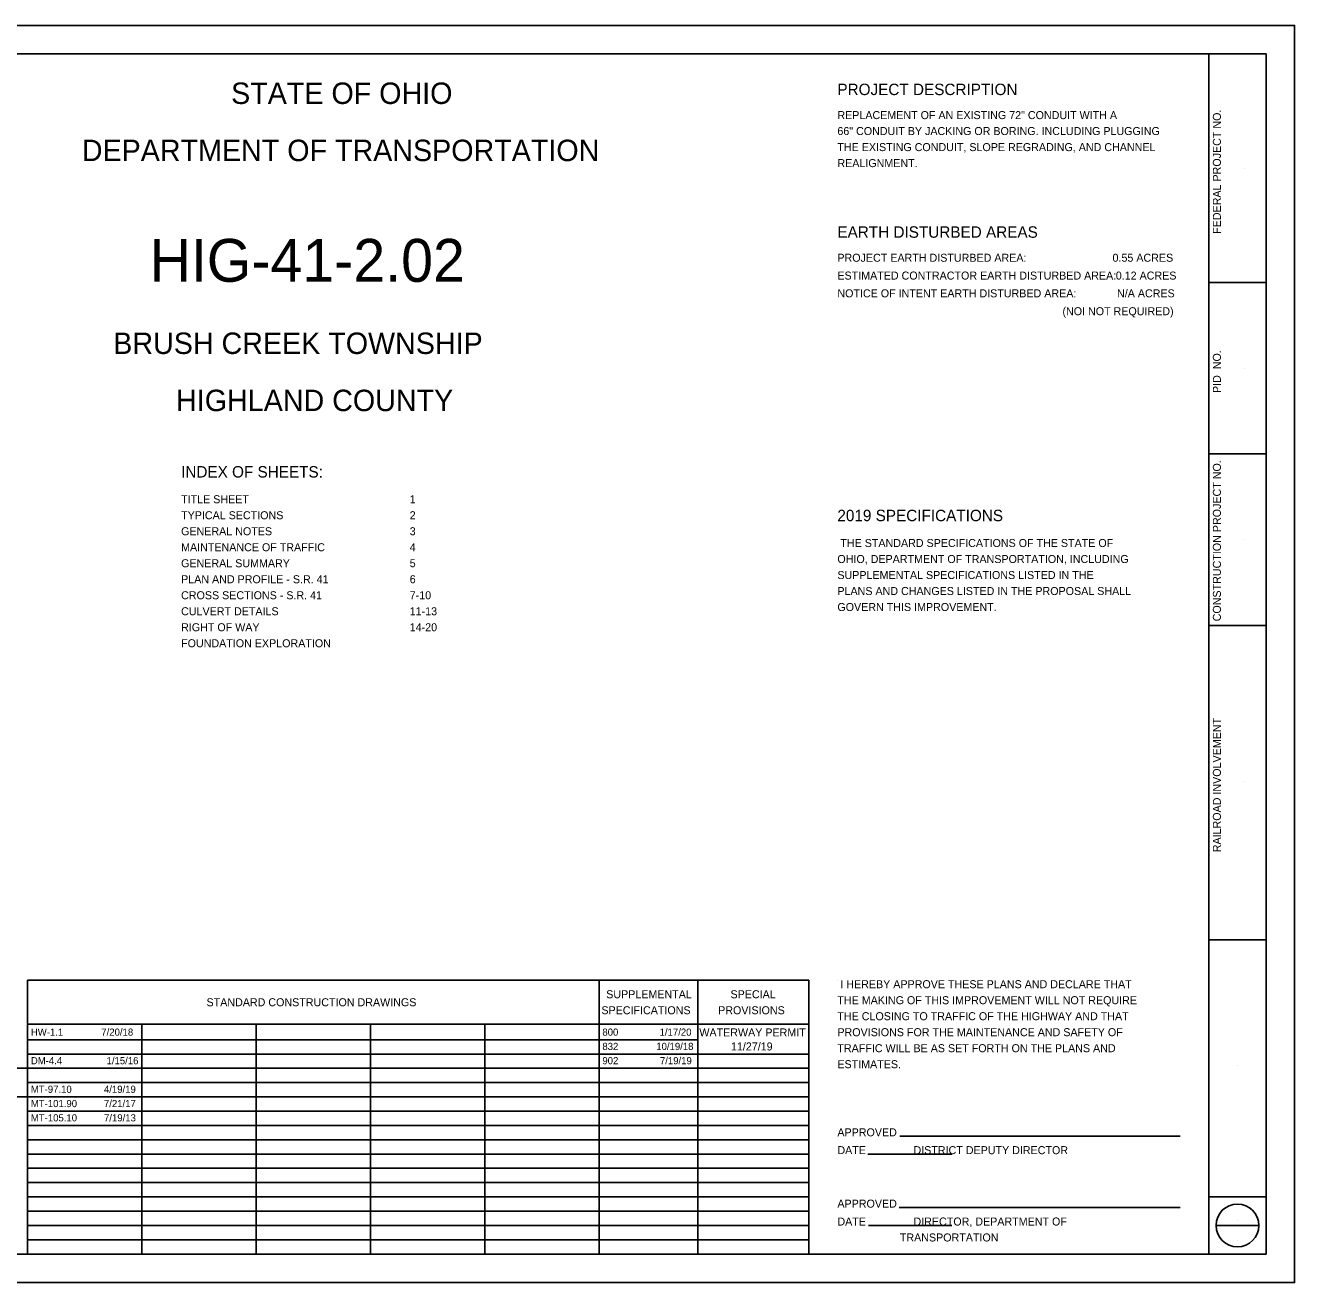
# Model space of a CAD drawing. Extents: x 0 to 34, y 0 to 22.
# Drawn here: x 11.79 to 34, y 0 to 22 of the extents above; entities that cross this region are included whole.
import ezdxf

# ---------------------------------------------------------------- set-up
doc = ezdxf.new("R2010")
doc.units = 0
for name, color, linetype in [('SH_Border', 7, 'Continuous'), ('SH_Cut_Line', 7, 'Continuous'), ('SH_Data', 7, 'Continuous')]:
    doc.layers.add(name, color=color, linetype=linetype)

msp = doc.modelspace()

# ---------------------------------------------------------------- linework, layer by layer
at = {"layer": 'SH_Border'}
for p, q in [((32.5, 0.5), (32.5, 21.5)), ((32.5, 17.5), (33.5, 17.5)), ((32.5, 14.5), (33.5, 14.5)), ((32.5, 11.5), (33.5, 11.5)), ((32.5, 6), (33.5, 6)), ((32.5, 1.5), (33.5, 1.5))]:
    msp.add_line(p, q, dxfattribs=at)
msp.add_lwpolyline([(2, 21.5), (33.5, 21.5), (33.5, 0.5), (2, 0.5)], close=True, dxfattribs=at)
at = {"layer": 'SH_Cut_Line'}
msp.add_lwpolyline([(0, 0), (34, 0), (34, 22), (0, 22)], close=True, dxfattribs=at)
at = {"layer": 'SH_Data'}
for p, q in [((33.125, 19.5), (33.125, 19.5)), ((33.125, 16), (33.125, 16)), ((33.125, 13), (33.125, 13)), ((33.125, 8.766), (33.125, 8.766)), ((11.832, 5.292), (25.5, 5.292)), ((11.832, 0.5), (11.832, 5.292)), ((21.832, 0.5), (21.832, 5.292)), ((23.557, 0.5), (23.557, 5.292)), ((25.5, 0.5), (25.5, 5.292)), ((26, 5.292), (26, 5.292)), ((11.832, 4.521), (25.5, 4.521)), ((13.832, 0.5), (13.832, 4.521)), ((15.832, 0.5), (15.832, 4.521)), ((17.832, 0.5), (17.832, 4.521)), ((19.832, 0.5), (19.832, 4.521)), ((11.832, 4.25), (23.557, 4.25)), ((11.832, 4), (25.5, 4)), ((33, 3.799), (33, 3.799)), ((9.032, 3.75), (11.832, 3.75)), ((11.832, 3.75), (25.5, 3.75)), ((11.832, 3.5), (25.5, 3.5)), ((9.032, 3.25), (11.832, 3.25)), ((11.832, 3.25), (25.5, 3.25)), ((11.832, 3), (25.5, 3)), ((11.832, 2.75), (25.5, 2.75)), ((11.832, 2.5), (25.5, 2.5)), ((27.095, 2.56), (32, 2.56)), ((11.832, 2.25), (25.5, 2.25)), ((26.533, 2.248), (28, 2.248)), ((11.832, 2), (25.5, 2)), ((11.832, 1.75), (25.5, 1.75)), ((11.832, 1.5), (25.5, 1.5)), ((11.832, 1.25), (25.5, 1.25)), ((27.08, 1.312), (32, 1.312)), ((11.832, 1), (25.5, 1)), ((26.542, 0.999), (28, 0.999)), ((32.625, 1), (33.375, 1)), ((33, 1.085), (33, 1.085)), ((11.832, 0.75), (25.5, 0.75)), ((33, 0.745), (33, 0.745))]:
    msp.add_line(p, q, dxfattribs=at)
msp.add_circle((33, 1), 0.375, dxfattribs=at)

# ---------------------------------------------------------------- texts
for s, height, p in [('STATE OF OHIO', 0.375, (15.392, 20.625)), ('PROJECT DESCRIPTION', 0.2, (26, 20.78)), ('REPLACEMENT OF AN EXISTING 72" CONDUIT WITH A', 0.14, (26, 20.36)), ('66" CONDUIT BY JACKING OR BORING. INCLUDING PLUGGING', 0.14, (26, 20.081)), ('DEPARTMENT OF TRANSPORTATION', 0.375, (12.78, 19.625)), ('THE EXISTING CONDUIT, SLOPE REGRADING, AND CHANNEL', 0.14, (26, 19.8)), ('REALIGNMENT.', 0.14, (26, 19.52)), ('EARTH DISTURBED AREAS', 0.2, (26, 18.284)), ('HIG-41-2.02', 0.75, (13.964, 17.513)), ('PROJECT EARTH DISTURBED AREA:', 0.14, (26, 17.864)), ('0.55 ACRES', 0.14, (30.814, 17.864)), ('ESTIMATED CONTRACTOR EARTH DISTURBED AREA:', 0.14, (26, 17.552)), ('0.12 ACRES', 0.14, (30.871, 17.552)), ('NOTICE OF INTENT EARTH DISTURBED AREA:', 0.14, (26, 17.241)), ('N/A ACRES', 0.14, (30.893, 17.241)), ('(NOI NOT REQUIRED)', 0.14, (29.938, 16.928)), ('BRUSH CREEK TOWNSHIP', 0.375, (13.33, 16.25)), ('HIGHLAND COUNTY', 0.375, (14.43, 15.25)), ('INDEX OF SHEETS:', 0.2, (14.517, 14.088)), ('TITLE SHEET', 0.14, (14.517, 13.638)), ('1', 0.14, (18.517, 13.638)), ('TYPICAL SECTIONS', 0.14, (14.517, 13.358)), ('2', 0.14, (18.517, 13.358)), ('2019 SPECIFICATIONS', 0.2, (26, 13.324)), ('GENERAL NOTES', 0.14, (14.517, 13.078)), ('3', 0.14, (18.517, 13.078)), ('MAINTENANCE OF TRAFFIC', 0.14, (14.517, 12.798)), ('4', 0.14, (18.517, 12.798)), (' THE STANDARD SPECIFICATIONS OF THE STATE OF', 0.14, (26, 12.872)), ('GENERAL SUMMARY', 0.14, (14.517, 12.518)), ('OHIO, DEPARTMENT OF TRANSPORTATION, INCLUDING', 0.14, (26, 12.592)), ('5', 0.14, (18.517, 12.518)), ('SUPPLEMENTAL SPECIFICATIONS LISTED IN THE', 0.14, (26, 12.312)), ('PLAN AND PROFILE - S.R. 41', 0.14, (14.517, 12.238)), ('6', 0.14, (18.517, 12.238)), ('CROSS SECTIONS - S.R. 41', 0.14, (14.517, 11.958)), ('7-10', 0.14, (18.517, 11.958)), ('PLANS AND CHANGES LISTED IN THE PROPOSAL SHALL', 0.14, (26, 12.032)), ('CULVERT DETAILS', 0.14, (14.517, 11.678)), ('11-13', 0.14, (18.517, 11.678)), ('GOVERN THIS IMPROVEMENT.', 0.14, (26, 11.752)), ('RIGHT OF WAY', 0.14, (14.517, 11.398)), ('14-20', 0.14, (18.517, 11.398)), ('FOUNDATION EXPLORATION', 0.14, (14.517, 11.118)), ('SUPPLEMENTAL', 0.14, (21.955, 4.976)), ('SPECIAL', 0.14, (24.13, 4.976)), (' I HEREBY APPROVE THESE PLANS AND DECLARE THAT', 0.14, (26, 5.152)), ('STANDARD CONSTRUCTION DRAWINGS', 0.14, (14.962, 4.836)), ('THE MAKING OF THIS IMPROVEMENT WILL NOT REQUIRE', 0.14, (26, 4.872)), ('SPECIFICATIONS', 0.14, (21.871, 4.696)), ('PROVISIONS', 0.14, (23.914, 4.696)), ('THE CLOSING TO TRAFFIC OF THE HIGHWAY AND THAT', 0.14, (26, 4.592)), ('HW-1.1', 0.125, (11.888, 4.321)), ('7/20/18', 0.125, (13.121, 4.321)), ('800', 0.125, (21.888, 4.321)), ('1/17/20', 0.125, (22.889, 4.321)), ('WATERWAY PERMIT', 0.14, (23.585, 4.308)), ('PROVISIONS FOR THE MAINTENANCE AND SAFETY OF', 0.14, (26, 4.312)), ('832', 0.125, (21.888, 4.071)), ('10/19/18', 0.125, (22.831, 4.071)), ('11/27/19', 0.14, (24.138, 4.063)), ('TRAFFIC WILL BE AS SET FORTH ON THE PLANS AND', 0.14, (26, 4.032)), ('DM-4.4', 0.125, (11.888, 3.821)), ('1/15/16', 0.125, (13.213, 3.821)), ('902', 0.125, (21.888, 3.821)), ('7/19/19', 0.125, (22.895, 3.821)), ('ESTIMATES.', 0.14, (26, 3.752)), ('MT-97.10', 0.125, (11.888, 3.321)), ('4/19/19', 0.125, (13.167, 3.321)), ('MT-101.90', 0.125, (11.888, 3.071)), ('7/21/17', 0.125, (13.167, 3.071)), ('MT-105.10', 0.125, (11.888, 2.821)), ('7/19/13', 0.125, (13.168, 2.821)), ('APPROVED', 0.14, (26, 2.56)), ('DATE                DISTRICT DEPUTY DIRECTOR', 0.14, (26, 2.248)), ('APPROVED', 0.14, (26, 1.312)), ('DATE                DIRECTOR, DEPARTMENT OF', 0.14, (26, 0.999)), ('                     TRANSPORTATION', 0.14, (26, 0.72))]:
    msp.add_text(s, height=height, dxfattribs=at).set_placement(p)
for s, p in [('FEDERAL PROJECT NO.', (32.71, 18.352)), ('PID  NO.', (32.71, 15.567)), ('CONSTRUCTION PROJECT NO.', (32.71, 11.572)), ('RAILROAD INVOLVEMENT', (32.71, 7.531))]:
    msp.add_text(s, height=0.14, rotation=90, dxfattribs=at).set_placement(p)

doc.saveas('drawing.dxf')
